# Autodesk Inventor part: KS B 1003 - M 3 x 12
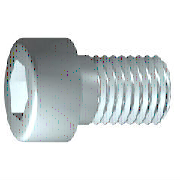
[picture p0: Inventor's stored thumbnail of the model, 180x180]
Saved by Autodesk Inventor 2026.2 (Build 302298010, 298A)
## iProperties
Created: 2025-01
Part Number: KS B 1003 - M 3 x 12
Material: 강철, 연강
Description: 6각머리 태핑 나사
Document SubType Name: Modeling
Standard: KS B 1003
Designer: work
Standards Organization: KS
Language: ko-KR
Size Designation: M 3 x 12
Categories: <MemberInstance><Categories><Category DisplayName="조임쇠" InternalName="e4da775c-781d-43d5-af7c-5136215cf5a6" Mnemonic="FSTN"><Category DisplayName="볼트" InternalN
Density: 7.85 g/cm^3
Appearance: 반연마
IsCustomPart: 1
Author: work
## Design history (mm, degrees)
body "Solid1"
workplane "Work Plane1"
fillet "Fillet2" dims "d30" = 0.1 (= R)
revolve "본체" stored, may be unused: angle "d10" = 90 deg
sketch "스케치2"
  geometry: L1 (0, -3.85)-(0, 3.85) reference; L2 (-3.85, 0)-(3.85, 0) reference; L3 (1.443, 0)-(0.722, -1.25); L4 (0.722, -1.25)-(-0.722, -1.25); L5 (-0.722, -1.25)-(-1.443, 0); L6 (-1.443, 0)-(-0.722, 1.25); L7 (-0.722, 1.25)-(0.722, 1.25); L8 (0.722, 1.25)-(1.443, 0); 2 further points
  constraints: 12 end point, 1 coincident, 1 horizontal alignment, 1 point on line, 12 other
extrude "슬롯" join sketch "스케치2" stored distance "d11" = 10; taper "d12" = 0 deg
fillet "모깎기1" dims "d17" = 0.3 (= RR)
feature "스레드" dims "d13" = 10.75 (= GEL), "d14" = 0
chamfer "모따기1" distance "d15" = 0.30673 (= -0.5 x SPD + 0.5 x GD); stored, may be unused: second distance "d16" = 0.30673 (= GUL), angle "d27" = 45 deg
sketch "스케치1"
  geometry: L1 (-0.867, 0)-(12, 0); L2 (12, 0)-(12, 1.5); L3 (12, 1.5)-(1.25, 1.5); L4 (1.25, 1.5)-(0.943, 1.5); L5 (0.943, 1.5)-(0, 1.5); L6 (0, 1.5)-(0, 2.75); L7 (0, 2.75)-(-3, 2.75); L8 (-3, 2.75)-(-3, 1.443); L9 (-3, 1.443)-(-1.7, 1.443); L10 (-1.7, 1.443)-(-0.867, 0); L11 (-6, 0)-(15, 0) reference; L12 (0, -0.55)-(0, 3.3) reference; L13 (1.25, 1.5)-(0, 1.5)
  constraints: 22 end point, 6 parallel, 2 collinear, 2 perpendicular, 1 horizontal, 1 point on line
  dimensions: "d1" = 10.75 distance from line of L3.end L2 (= GEL); "d2" = 0.30683 distance of L4.end L3.end (computed from GAL); "d3" = 3 distance between parallel lines of L8 L6 (= KOH); "d4" = 1.3 distance of L8.end L9.end (= INTI); "d5" = 60 deg angle of L10 L1; "d6" = 3 diameter of L3 L1 (= GD); "d7" = 3 diameter of L5 L1 (= BDM); "d8" = 2.88675 diameter of L9 L1 (= 1.1547 x SW); "d9" = 5.5 diameter of L7 L1 (= KOD); "d26" = 12 distance between parallel lines of L12 L2 (= NLG)
other parameters: "GD" = 3 (= NND) [user parameter; used in 2 equation terms], "NLG" = 12 [user parameter; used in 1 equation term], "GEL" = 10.75 [user parameter; used in 2 equation terms], "KOD" = 5.5 [user parameter; used in 1 equation term], "KOH" = 3 [user parameter; used in 1 equation term], "INTI" = 1.3 [user parameter; used in 1 equation term], "GAL" = 0.30673 (= 0.61345 x PTC) [user parameter; used in 1 equation term], "GUL" = 0.30673 (= 0.61345 x PTC) [user parameter; used in 1 equation term], "BDM" = 3 (= NND) [user parameter; used in 1 equation term], "SW" = 2.5 [user parameter; used in 2 equation terms], "RR" = 0.3 [user parameter; used in 1 equation term], "SPD" = 2.38655 (= NND - 1.2269 x PTC) [user parameter; used in 1 equation term], "d19" = 0, "d28" = 0, "d29" = 0, "R" = 0.1 [user parameter; used in 1 equation term], "PHH" = 0.1 [user parameter], "GD1" = 2.38655 (= THREADDIA - 1.2269 x PTC) [user parameter], "THREADDIA" = 3 [user parameter; used in 1 equation term], "FAWI" = 45 deg [user parameter], "PTC" = 0.5 [user parameter; used in 5 equation terms], "NND" = 3 [user parameter; used in 3 equation terms], "TOA" = 30 deg [user parameter], "E0" = 2.8875 (= 1.155 x SW) [user parameter]
